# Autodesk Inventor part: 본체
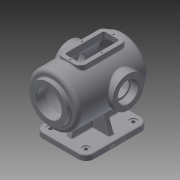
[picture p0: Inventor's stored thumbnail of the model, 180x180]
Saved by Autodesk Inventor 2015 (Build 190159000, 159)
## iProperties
Created: 2021-11
Part Number: 본체
Material: 일반
Document SubType Name: Modeling
Designer: G01
Density: 1 g/cm^3
Appearance: 기본값
Author: G01
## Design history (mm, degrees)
sketch "스케치1"
  geometry: L1 (-65, -80)-(65, -80); L2 (65, -80)-(65, 80); L3 (65, 80)-(-65, 80); L4 (-65, 80)-(-65, -80); L5 (-65, -80)-(65, 80); L6 (65, -80)-(-65, 80); 1 further point
  constraints: 12 end point, 2 midpoint, 2 parallel, 1 horizontal, 1 perpendicular
  dimensions: "d0" = 130 distance of L1.start L1.end; "d1" = 160 distance of L3.end L1.start
extrude "돌출1" new body sketch "스케치1" distance "d2" = 14; taper "d3" = 0 deg
fillet "모깎기1" dims "d4" = 20
fillet "모깎기2" dims "d5" = 3
sketch "스케치2"
  geometry: A1 r 17 centre (45, -60) between (45, -77) and (62, -60) reference; A2 r 17 centre (45, 60) between (62, 60) and (45, 77) reference; A3 r 17 centre (-45, 60) between (-45, 77) and (-62, 60) reference; A4 r 17 centre (-45, -60) between (-62, -60) and (-45, -77) reference; 1 further point
hole "구멍1" sketch "스케치2" at (-45, -60), (45, -60), (45, 60), (-45, 60) diameter "d6" = 9; stored, may be unused: countersink angle "d10" = 90 deg, drill point angle "d12" = 118 deg; dims "d7" = 6, "d8" = 18, "d9" = 2, "d11" = 8
sketch "스케치3"
  geometry: L1 (-65, 60)-(-65, -60) reference; L2 (-45, -80)-(45, -80) reference; L3 (45, 80)-(-45, 80) reference; L4 (65, -60)-(65, 60) reference; L5 (-7, -60)-(7, -60); L6 (7, -60)-(7, 60); L7 (7, 60)-(-7, 60); L8 (-7, 60)-(-7, -60); L9 (-7, -60)-(7, 60); L10 (7, -60)-(-7, 60); L11 (-50, -7)-(50, -7); L12 (50, -7)-(50, 7); L13 (50, 7)-(-50, 7); L14 (-50, 7)-(-50, -7); L15 (-50, -7)-(50, 7); L16 (50, -7)-(-50, 7); 1 further point
  constraints: 24 end point, 4 midpoint, 4 parallel, 2 horizontal, 2 perpendicular
  dimensions: "d13" = 14 distance of L5.start L5.end; "d14" = 14 distance of L13.end L11.start; "d15" = 100 distance of L12.end L13.end; "d16" = 120 distance of L5.end L6.end
extrude "돌출2" join sketch "스케치3" distance "d17" = 100; taper "d18" = 0 deg
feature "면 기울기1" dims angle "d19" = 20 deg
feature "면 기울기2" dims angle "d20" = 20 deg
feature "면 기울기3" dims angle "d21" = 20 deg
feature "면 기울기4" dims angle "d22" = 20 deg
fillet "모깎기7" dims "d70" = 3
fillet "모깎기8" dims "d71" = 3
sketch "스케치4"
  geometry: L1 (80, 11)-(80, 0) reference; L2 (80, 0)-(-80, 0) reference; L3 (-80, 0)-(-80, 11) reference; L4 (-77, 14)-(-62.101, 14) reference; L5 (-59.282, 15.974)-(-23.603, 114) reference; L6 (-23.603, 114)-(23.603, 114) reference; L7 (23.603, 114)-(59.282, 15.974) reference; L8 (62.101, 14)-(77, 14) reference; L9 (100, 114)-(-110, 114); L10 (-110, 114)-(-110, 161.5); L11 (-110, 161.5)-(-100, 161.5); L12 (-100, 161.5)-(-100, 179); L13 (-100, 179)-(75.993, 179); A1 r 3 centre (77, 11) between (80, 11) and (77, 14) reference; A2 r 3 centre (-77, 11) between (-77, 14) and (-80, 11) reference; A3 r 100 centre (0, 114) between (100, 114) and (75.993, 179); A4 r 3 centre (-62.101, 17) between (-62.101, 14) and (-59.282, 15.974) reference; A5 r 3 centre (62.101, 17) between (59.282, 15.974) and (62.101, 14) reference; 3 further points
  constraints: 10 end point, 2 horizontal, 2 midpoint, 2 perpendicular, 2 point on circle, 1 centre point, 1 coincident, 1 point on line, 1 vertical
  dimensions: "d24" = 210 distance of L9.start L9.end; "d25" = 47.5 distance of L9.end L10.end; "d26" = 10 distance of L10.end L11.end; "d28" = 110 distance from line of point (0, 114) L10; "d29" = 65 distance between parallel lines of L9 L13; "d30" = 100 radius of A3
revolve "회전1" sketch "스케치4" stored, may be unused: angle "d31" = 90 deg
sketch "스케치5"
  geometry: L1 (60, 0)-(-60, 0) reference; L2 (-110, 66.5)-(-110, 161.5) reference; L3 (-100, 66.5)-(-100, 161.5) reference; L4 (-110, 114)-(-110, 146.5); L5 (-85, 146.5)-(-85, 169); L6 (-110, 146.5)-(-85, 146.5); L7 (-85, 169)-(71.239, 169); L8 (-110, 114)-(90, 114); L9 (-100, 179)-(75.993, 179) reference; L10 (-110, 161.5)-(-100, 161.5) reference; A1 r 100 centre (0, 114) between (75.993, 49) and (75.993, 179) reference; A2 r 90 centre (0, 114) between (90, 114) and (71.239, 169); 1 further point
  constraints: 10 end point, 3 horizontal, 2 point on circle, 1 centre point, 1 midpoint, 1 point on line, 1 vertical
  dimensions: "d32" = 10 radial gap between concentric circles of A1 A2; "d33" = 25 distance between parallel lines of L5 L2; "d34" = 55 distance between parallel lines of L8 L7; "d35" = 32.5 distance between parallel lines of L8 L6; "d36" = 114 distance between parallel lines of L1 L8
revolve "회전2" sketch "스케치5" stored, may be unused: angle "d37" = 90 deg
fillet "모깎기3" dims "d38" = 3
node "작업 평면1"
sketch "스케치6"
  geometry: L1 (30, -60)-(-30, -60); L2 (-30, -60)-(-30, 60); L3 (-30, 60)-(30, 60); L4 (30, 60)-(30, -60); L5 (30, -60)-(-30, 60); L6 (-30, -60)-(30, 60); L7 (47.5, -110)-(-47.5, -110) reference; 3 further points
  constraints: 12 end point, 3 midpoint, 2 parallel, 1 coincident, 1 horizontal, 1 perpendicular
  dimensions: "d40" = 50 distance between parallel lines of L1 L7; "d41" = 60 distance of L2.end L3.end; "d42" = 120 distance of L3.end L1.start
extrude "돌출3" join sketch "스케치6" stored distance "d43" = 10; taper "d44" = 0 deg
fillet "모깎기4" dims "d45" = 15
fillet "모깎기5" dims "d46" = 3
sketch "스케치7"
  geometry: L1 (-15, -60)-(15, -60) reference; L2 (30, -45)-(30, 45) reference; L3 (15, 60)-(-15, 60) reference; L4 (-30, 45)-(-30, -45) reference; L5 (-15, -50)-(15, -50); L6 (20, -45)-(20, 45); L7 (15, 50)-(-15, 50); L8 (-20, 45)-(-20, -45); A1 r 15 centre (-15, -45) between (-30, -45) and (-15, -60) reference; A2 r 15 centre (15, -45) between (15, -60) and (30, -45) reference; A3 r 15 centre (15, 45) between (30, 45) and (15, 60) reference; A4 r 15 centre (-15, 45) between (-15, 60) and (-30, 45) reference; A5 r 5 centre (-15, -45) between (-20, -45) and (-15, -50); A6 r 5 centre (15, -45) between (15, -50) and (20, -45); A7 r 5 centre (15, 45) between (20, 45) and (15, 50); A8 r 5 centre (-15, 45) between (-15, 50) and (-20, 45); 1 further point
  constraints: 8 end point, 8 point on circle, 4 centre point, 7 other
  dimensions: "d47" = 10 distance between parallel lines of L8 L4
extrude "돌출4" cut sketch "스케치7" distance "d48" = 50; taper "d49" = 0 deg
sketch "스케치8"
  geometry: L1 (-15, -60)-(15, -60) reference; L2 (30, -45)-(30, 45) reference; L3 (15, 60)-(-15, 60) reference; L4 (-30, 45)-(-30, -45) reference; L5 (-15, -55)-(15, -55); L6 (25, -45)-(25, 45); L7 (15, 55)-(-15, 55); L8 (-25, 45)-(-25, -45); A1 r 15 centre (-15, -45) between (-30, -45) and (-15, -60) reference; A2 r 15 centre (15, -45) between (15, -60) and (30, -45) reference; A3 r 15 centre (15, 45) between (30, 45) and (15, 60) reference; A4 r 15 centre (-15, 45) between (-15, 60) and (-30, 45) reference; A5 r 10 centre (-15, -45) between (-25, -45) and (-15, -55); A6 r 10 centre (15, -45) between (15, -55) and (25, -45); A7 r 10 centre (15, 45) between (25, 45) and (15, 55); A8 r 10 centre (-15, 45) between (-15, 55) and (-25, 45); 5 further points
  constraints: 8 end point, 8 point on circle, 4 centre point, 4 midpoint, 7 other
  dimensions: "d50" = 5 distance between parallel lines of L8 L4
hole "구멍2" sketch "스케치8" at (0, -55), (0, 55), (-25, 0), (25, 0) diameter "d51" = 3.242; stored, may be unused: countersink angle "d55" = 90 deg, drill point angle "d57" = 118 deg; dims "d52" = 9, "d53" = 4, "d54" = 2, "d56" = 11
fillet "모깎기6" dims "d58" = 3
sketch "스케치9"
  geometry: C1 r 32.5 at (0, 0) reference; 2 further points
  constraints: 1 vertical alignment
  dimensions: "d59" = 40 distance of C1.centre point (0, 40)
hole "구멍3" sketch "스케치9" at (0, 40) diameter "d60" = 3.242; stored, may be unused: countersink angle "d64" = 90 deg, drill point angle "d66" = 118 deg; dims "d61" = 11, "d62" = 4, "d63" = 2, "d65" = 13
sketch "스케치10"
  geometry: L1 (-60, 182)-(-60, 184) reference; L2 (-60, 184)-(-56.621, 184) reference; L3 (-56.621, 184)-(-56.621, 173) reference; L4 (-56.621, 173)-(-55, 172.026) reference; L5 (-55, 172.026)-(-53.379, 173) reference; L6 (-53.379, 173)-(-53.379, 184) reference; L7 (-53.379, 184)-(-50, 184) reference; L8 (-50, 184)-(-50, 172) reference; L9 (-53, 169)-(-82, 169) reference; L10 (-85, 166)-(-85, 146.5) reference; L11 (-85, 146.5)-(-110, 146.5) reference; L12 (-110, 146.5)-(-110, 152.379) reference; L13 (-110, 152.379)-(-97, 152.379) reference; L14 (-97, 152.379)-(-96.026, 154) reference; L15 (-96.026, 154)-(-97, 155.621) reference; L16 (-97, 155.621)-(-110, 155.621) reference; L17 (-110, 155.621)-(-110, 161.5) reference; L18 (-110, 161.5)-(-100, 161.5) reference; L19 (-100, 161.5)-(-100, 179) reference; L20 (-100, 179)-(-63, 179) reference; L21 (80, 0)-(-80, 0) reference; L22 (-80, 0)-(-80, 11) reference; L23 (-77, 14)-(-62.101, 14) reference; L24 (-59.282, 15.974)-(-47.261, 49) reference; L25 (-47.261, 49)-(-100, 49) reference; L26 (-100, 49)-(-100, 66.5) reference; L27 (-100, 66.5)-(-110, 66.5) reference; L28 (-110, 66.5)-(-110, 72.379) reference; L29 (-110, 72.379)-(-97, 72.379) reference; L30 (-97, 72.379)-(-96.026, 74) reference; L31 (-96.026, 74)-(-97, 75.621) reference; L32 (-97, 75.621)-(-110, 75.621) reference; L33 (-110, 75.621)-(-110, 81.5) reference; L34 (-110, 81.5)-(-85, 81.5) reference; L35 (-85, 81.5)-(-85, 62) reference; L36 (-82, 59)-(69.75, 59) reference; L37 (69.75, 169)-(53, 169) reference; L38 (50, 172)-(50, 184) reference; L39 (50, 184)-(53.379, 184) reference; L40 (53.379, 184)-(53.379, 173) reference; L41 (53.379, 173)-(55, 172.026) reference; L42 (55, 172.026)-(56.621, 173) reference; L43 (56.621, 173)-(56.621, 184) reference; L44 (56.621, 184)-(60, 184) reference; L45 (60, 184)-(60, 182) reference; L46 (63, 179)-(75.993, 179) reference; L47 (75.993, 49)-(47.261, 49) reference; L48 (47.261, 49)-(59.282, 15.974) reference; L49 (62.101, 14)-(77, 14) reference; L50 (80, 11)-(80, 0) reference; C1 r 21 at (17, 114); A1 r 3 centre (-63, 182) between (-63, 179) and (-60, 182) reference; A2 r 3 centre (-53, 172) between (-53, 169) and (-50, 172) reference; A3 r 3 centre (-82, 166) between (-82, 169) and (-85, 166) reference; A4 r 3 centre (-77, 11) between (-77, 14) and (-80, 11) reference; A5 r 3 centre (-62.101, 17) between (-62.101, 14) and (-59.282, 15.974) reference; A6 r 3 centre (-82, 62) between (-85, 62) and (-82, 59) reference; A7 r 3 centre (69.75, 62) between (69.75, 59) and (72.155, 60.207) reference; A8 r 90 centre (0, 114) between (72.155, 60.207) and (72.155, 167.793) reference; A9 r 3 centre (69.75, 166) between (72.155, 167.793) and (69.75, 169) reference; A10 r 3 centre (53, 172) between (50, 172) and (53, 169) reference; A11 r 3 centre (63, 182) between (60, 182) and (63, 179) reference; A12 r 100 centre (0, 114) between (75.993, 49) and (75.993, 179) reference; A13 r 3 centre (62.101, 17) between (59.282, 15.974) and (62.101, 14) reference; A14 r 3 centre (77, 11) between (80, 11) and (77, 14) reference; 1 further point
  constraints: 1 centre point
  dimensions: "d72" = 42 diameter of C1; "d73" = 114 distance from line of L21 C1.centre; "d74" = 127 horizontal distance of C1.centre L17.end
  node "절단 모서리 투영2"
node "작업 평면2"
sketch "스케치11"
  geometry: L1 (-60, 0)-(60, 0) reference; L2 (-110, 66.5)-(-110, 161.5) reference; C1 r 40 at (17, 114); 1 further point
  constraints: 1 centre point
  dimensions: "d76" = 80 diameter of C1; "d77" = 127 distance from line of C1.centre L2; "d78" = 114 distance from line of L1 C1.centre
extrude "돌출5" join sketch "스케치11" stored distance "d79" = 150; taper "d80" = 0 deg
fillet "모깎기9" dims "d81" = 3
sketch "스케치12"
  geometry: C1 r 40 at (0, 0) reference; 1 further point
hole "구멍4" sketch "스케치12" at (0, 0) diameter "d82" = 42; stored, may be unused: countersink angle "d86" = 90 deg, drill point angle "d88" = 118 deg; dims "d83" = 42, "d84" = 52, "d85" = 18, "d87" = 13
sketch "스케치13"
  geometry: C1 r 21 at (0, 0) reference; C2 r 40 at (0, 0) reference; C3 r 26 at (0, 0); 1 further point
  constraints: 1 centre point, 1 coincident
  dimensions: "d89" = 52 diameter of C3
extrude "돌출6" cut sketch "스케치13" distance "d90" = 18; taper "d91" = 0 deg
fillet "모깎기10" dims "d92" = 0.3
sketch "스케치14"
  geometry: C1 r 26 at (0, 0) reference; 2 further points
  constraints: 1 horizontal alignment
  dimensions: "d93" = 32.5 distance of C1.centre point (-32.5, 0)
hole "구멍5" sketch "스케치14" at (-32.5, 0) diameter "d94" = 3.242; stored, may be unused: countersink angle "d98" = 90 deg, drill point angle "d100" = 118 deg; dims "d95" = 11, "d96" = 52, "d97" = 18, "d99" = 13
fillet "모깎기11" dims "d104" = 10
fillet "모깎기12" dims "d105" = 3
fillet "모깎기13" dims "d106" = 10
sketch "스케치15"
  geometry: L1 (0, 0)-(0, 120) reference; 4 further points
  constraints: 2 horizontal alignment, 2 midpoint, 1 other
  dimensions: "d107" = 5 distance from line of L1 point (-5, 60)
feature "엠보싱1" sketch "스케치15" dims "d108" = 0.5, "d109" = 0
chamfer "모따기1" distance "d110" = 1; stored, may be unused: second distance "d111" = 2, angle "d112" = 45 deg
chamfer "모따기2" distance "d113" = 1; stored, may be unused: second distance "d114" = 2, angle "d115" = 45 deg
node "솔리드1"
pattern_circular "원형 패턴1" dims angle "d68" = 360 deg
mirror "대칭1"
pattern_circular "원형 패턴2" dims angle "d102" = 360 deg
mirror "대칭2"
node "투영된 루프1"
node "절단 모서리 투영1"
other parameters: "d39" = -184, "d75" = 75
